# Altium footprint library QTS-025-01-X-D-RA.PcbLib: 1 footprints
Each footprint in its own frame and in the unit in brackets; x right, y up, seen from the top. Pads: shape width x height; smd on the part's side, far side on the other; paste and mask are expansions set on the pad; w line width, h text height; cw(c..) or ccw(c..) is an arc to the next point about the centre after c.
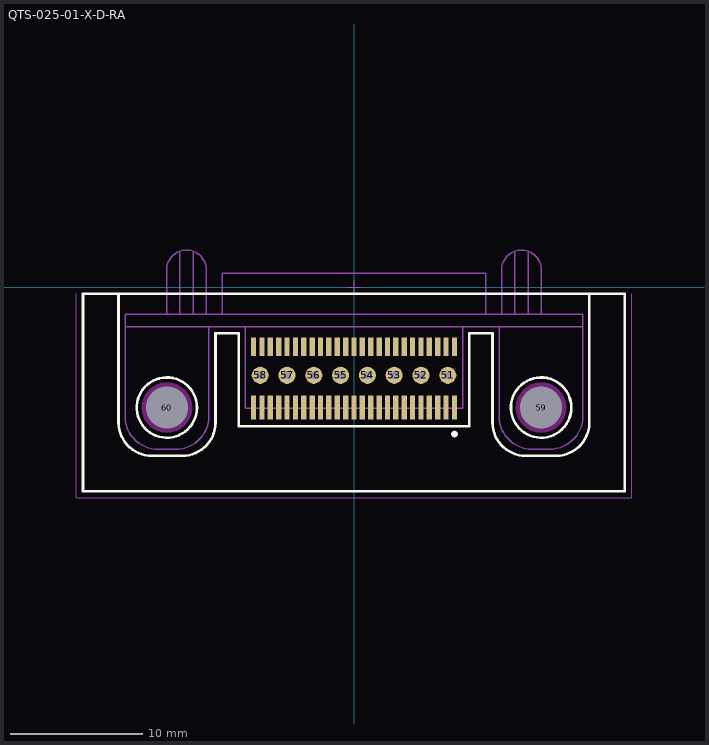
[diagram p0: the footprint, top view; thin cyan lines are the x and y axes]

## QTS-025-01-X-D-RA [mm] "0.635mm pitch, 50 pin, high speed terminal strip; r/a"
height 9.42
pads (60):
  rect 0.4x1.8 smd mask+0: 1(7.62,-9.144) 3(6.985,-9.144) 5(6.35,-9.144) 7(5.715,-9.144) 9(5.08,-9.144) 11(4.445,-9.144) 13(3.81,-9.144) 15(3.175,-9.144) 17(2.54,-9.144) 19(1.905,-9.144) 21(1.27,-9.144) 23(0.635,-9.144) 25(0,-9.144) 27(-0.635,-9.144) 29(-1.27,-9.144) 31(-1.905,-9.144) 33(-2.54,-9.144) 35(-3.175,-9.144) 37(-3.81,-9.144) 39(-4.445,-9.144) 41(-5.08,-9.144) 43(-5.715,-9.144) 45(-6.35,-9.144) 47(-6.985,-9.144) 49(-7.62,-9.144)
  rect 0.4x1.4 smd mask+0: 2(7.62,-4.534) 4(6.985,-4.534) 6(6.35,-4.534) 8(5.715,-4.534) 10(5.08,-4.534) 12(4.445,-4.534) 14(3.81,-4.534) 16(3.175,-4.534) 18(2.54,-4.534) 20(1.905,-4.534) 22(1.27,-4.534) 24(0.635,-4.534) 26(0,-4.534) 28(-0.635,-4.534) 30(-1.27,-4.534) 32(-1.905,-4.534) 34(-2.54,-4.534) 36(-3.175,-4.534) 38(-3.81,-4.534) 40(-4.445,-4.534) 42(-5.08,-4.534) 44(-5.715,-4.534) 46(-6.35,-4.534) 48(-6.985,-4.534) 50(-7.62,-4.534)
  round 1.3 hole 0.6 mask+0: 51(7.111,-6.693) 52(5.079,-6.693) 53(3.047,-6.693) 54(1.015,-6.693) 55(-1.017,-6.693) 56(-3.049,-6.693) 57(-5.081,-6.693) 58(-7.113,-6.693)
  round 1 hole 3.2 unplated mask+0: 59(14.191,-9.144) 60(-14.191,-9.144)
Top Overlay:
  circle w0.25: c7.62,-11.15 r0.125
  circle w0.2: c14.191,-9.144 r2.286
  circle w0.2: c-14.191,-9.144 r2.286
  lines w0.2: -17.856,-10.276 ccw(c-15.323,-10.267) -15.315,-12.8 ; -17.856,-10.274 -17.856,-0.508 17.85,-0.508 17.85,-10.274 cw(c15.315,-10.265) 15.315,-12.8 ; -15.316,-12.8 -13.03,-12.8 ; -13.032,-12.8 ccw(c-13.028,-10.272) -10.5,-10.276 ; -10.5,-10.274 -10.5,-3.5 -8.75,-3.5 -8.75,-10.55 8.738,-10.55 8.738,-3.518 10.5,-3.518 10.5,-10.274 ccw(c13.03,-10.27) 13.03,-12.8 15.316,-12.8 ; -20.55,-15.5 -20.55,-0.508 20.541,-0.508 20.541,-15.5 -20.55,-15.5
Keep-Out Layer:
  pour cut-out: 16.1,-9.144 16.064,-8.772 15.955,-8.413 15.778,-8.083 15.541,-7.794 15.252,-7.557 14.922,-7.38 14.563,-7.271 14.191,-7.235 13.819,-7.271 13.46,-7.38 13.13,-7.557 12.841,-7.794 12.604,-8.083 12.427,-8.413 12.318,-8.772 12.282,-9.144 12.318,-9.516 12.427,-9.875 12.604,-10.205 12.841,-10.494 13.13,-10.731 13.46,-10.908 13.819,-11.017 14.191,-11.053 14.563,-11.017 14.922,-10.908 15.252,-10.731 15.541,-10.494 15.778,-10.205 15.955,-9.875 16.064,-9.516
  pour cut-out: -12.282,-9.144 -12.318,-8.772 -12.427,-8.413 -12.604,-8.083 -12.841,-7.794 -13.13,-7.557 -13.46,-7.38 -13.819,-7.271 -14.191,-7.235 -14.563,-7.271 -14.922,-7.38 -15.252,-7.557 -15.541,-7.794 -15.778,-8.083 -15.955,-8.413 -16.064,-8.772 -16.1,-9.144 -16.064,-9.516 -15.955,-9.875 -15.778,-10.205 -15.541,-10.494 -15.252,-10.731 -14.922,-10.908 -14.563,-11.017 -14.191,-11.053 -13.819,-11.017 -13.46,-10.908 -13.13,-10.731 -12.841,-10.494 -12.604,-10.205 -12.427,-9.875 -12.318,-9.516
Mechanical 12:
  lines w0.001: -20.55,-15.5 20.55,-15.5 20.55,-0.5 10,-0.5 10,1.05 -10,1.05 -10,-0.5 -20.55,-0.5 -20.55,-15.5
Mechanical 13:
  circle w0.1: c-14.191,-9.144 r2.286
  circle w0.1: c14.191,-9.144 r2.286
  lines w0.1: -14.2,-2.05 -14.2,1.307 cw(c-12.7,1.307) -11.2,1.307 -11.2,-2.05 ; -13.2,-2.05 -13.2,2.714 ; -12.2,-2.05 -12.2,2.714 ; -11,-3 -11,-9.819 cw(c-13.499,-9.801) -13.516,-12.3 -14.866,-12.3 cw(c-14.875,-9.809) -17.366,-9.818 -17.366,-3 ; -10,-2.05 -10,1.05 10,1.05 10,-2.05 ; -8.25,-3 -8.25,-9.2 8.25,-9.2 8.25,-3 ; 11,-3 11,-9.819 ccw(c13.499,-9.801) 13.516,-12.3 14.866,-12.3 ; 11.2,-2.05 11.2,1.307 cw(c12.7,1.307) 14.2,1.307 14.2,-2.05 ; 12.2,-2.05 12.2,2.714 ; 13.2,-2.05 13.2,2.714 ; 14.867,-12.3 ccw(c14.867,-9.817) 17.35,-9.817 ; 17.35,-9.819 17.35,-3 ; -17.366,-3 -17.366,-2.05 17.35,-2.05 17.35,-3 ; -17.366,-3 17.35,-3
  text ".Designator" at 0,0 h1.52
Mechanical 15:
  lines w0.05: -21.05,-0.5 -21.05,-16 21.05,-16 21.05,-0.5 ; -0.5,0 0.5,0 ; 0,-0.5 0,0.5
Drill Drawing:
  lines w0.025: -24.13,0 24.13,0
